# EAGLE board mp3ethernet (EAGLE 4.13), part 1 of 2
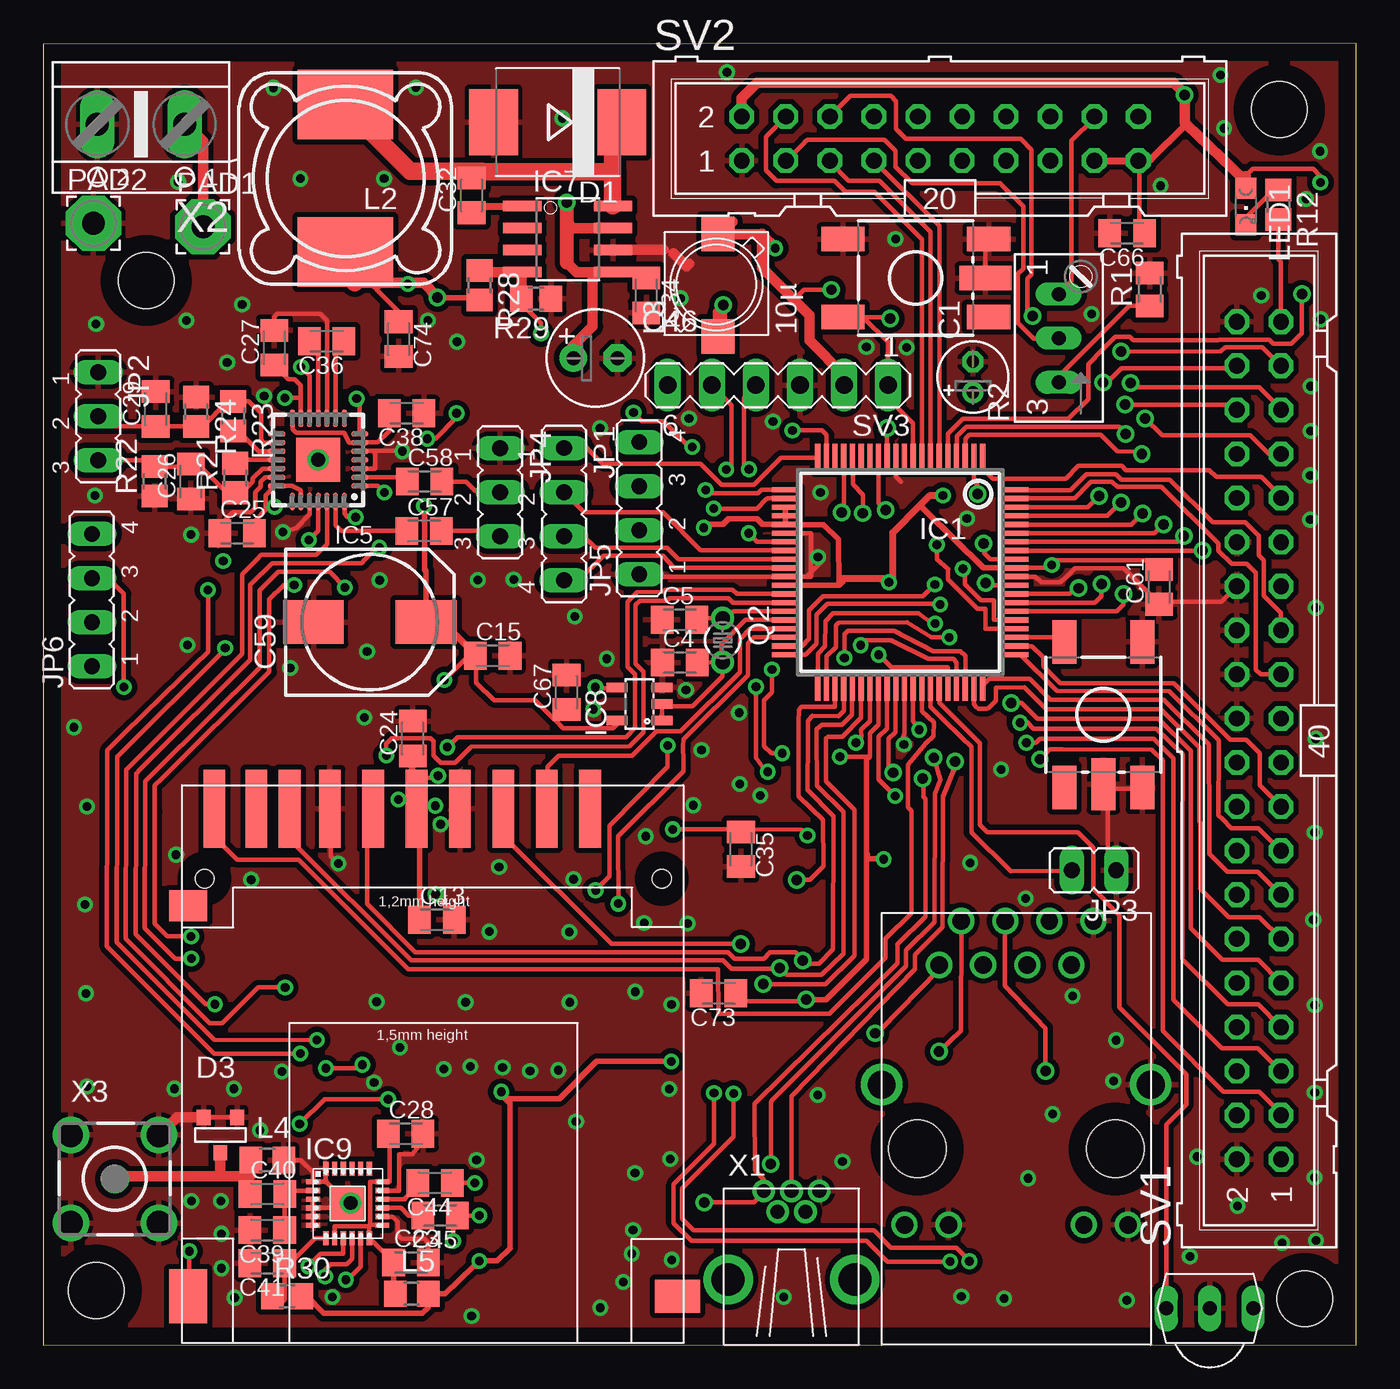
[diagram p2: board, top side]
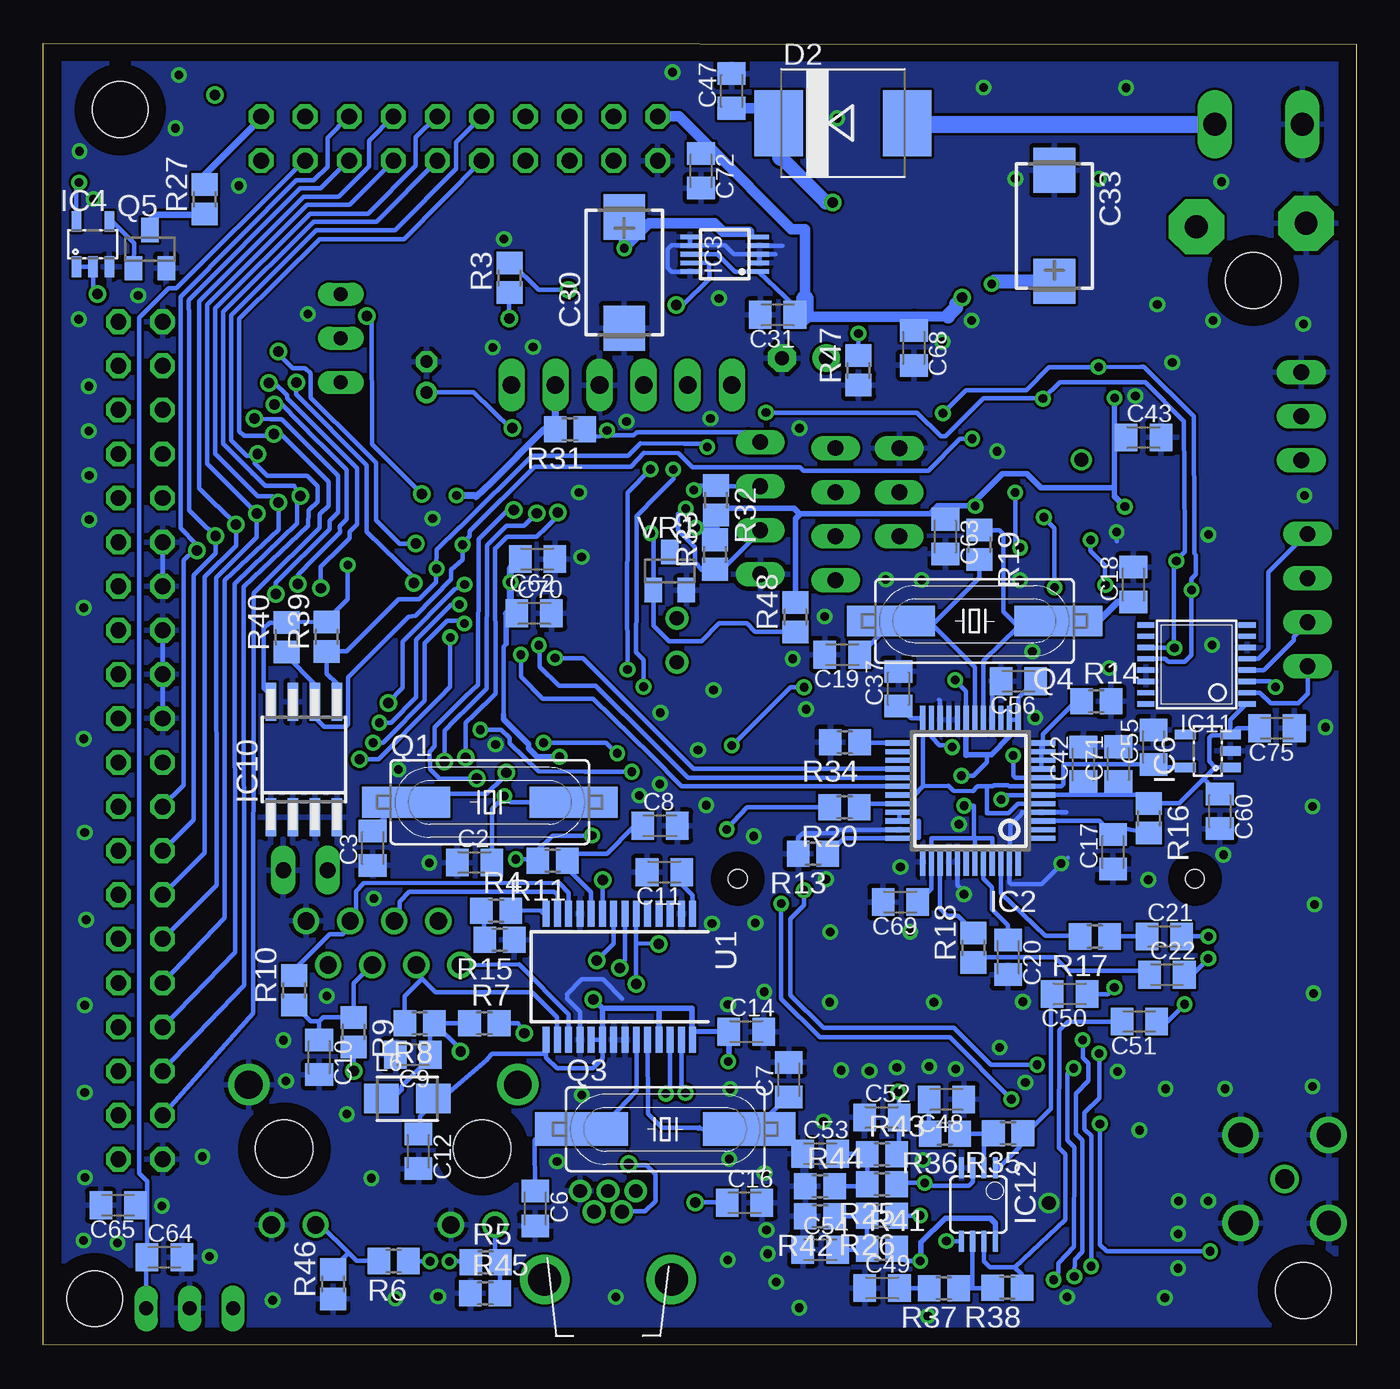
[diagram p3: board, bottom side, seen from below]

Size 75.66 x 75.02 mm. Coordinates in mm from the lower left corner, seen from the top.
Outline: 0,0 75.66,0.05 75.66,75.02 0,74.97 0,0
Copper layers (1*16): Top 0.035mm / dielectric 1.5mm / Bottom 0.035mm
Design rules "default": minimum track width 10mil, minimum drill 12mil, track to track 6mil, track to pad 6mil, pad to pad 6mil, via to via 6mil, smd to smd 0mil, copper to edge 40mil, drill to drill 8mil, minimum pad ring 10mil, minimum via ring 8mil, stop-mask expansion 2mil, vias tented up to drill 20mil, thermal gap 10mil
Holes 3.2 mm at 72.7,2.69 71.24,71.2 5.93,61.35 3.05,3.18

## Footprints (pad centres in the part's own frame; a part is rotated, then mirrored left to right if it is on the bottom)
1XRJ45_MM_JACK = drill 1 round: 1 4.445,-10.59; 2 3.175,-13.13; 3 1.905,-10.59; 4 0.635,-13.13; 5 -0.635,-10.59; 6 -1.905,-13.13; 7 -3.175,-10.59; 8 -4.445,-13.13; L1 3.9,4.38; L2 6.44,4.38; L3 -6.44,4.38; L4 -3.9,4.38 | drill 1.6 round: 9 7.75,-3.7; CASEGND -7.75,-3.7 | hole 3.3: 5.7,0; -5.7,0
E1,8-4 = drill 0.711 pad 1.168 round: + -0.889,0 | drill 0.711 pad 1.168 octagon: - 0.889,0
C0805K = smd 1.3 x 1.6: 1 -1,0; 2 1,0
CT7343 = smd 2.6 x 2.4: + 3.2,0; - -3.2,0
E2,5-6 = drill 0.813 pad 1.6 round: + -1.27,0 | drill 0.813 pad 1.6 octagon: - 1.27,0
150CLZ-0810 = smd 3.5 x 2.5: + 3.25,0; - -3.25,0
SDCA1A1401 = smd 1.25 x 4.5: 1 -6.63,4.04; 2 -9.13,4.04; 3 -11.63,4.04; 4 -14.13,4.04; 5 -16.63,4.04; 6 -19.13,4.04; 7 -21.45,4.04; 8 -23.36,4.04; 9 -4.13,4.04; 10 -25.79,4.04 | smd 2.2 x 1.8: 11 -27.3,-1.55 | smd 2.2 x 3.1: 12 -27.3,-24.05 | smd 2.6 x 1.9: 13 0.9,-24.05 | hole 1.06: 0,0; -26.35,0
SMC = smd 2.8 x 3.8: A 3.7,0; C -3.7,0
SOT-23 = smd 0.787 x 0.889: 1 0.025,-1.016; 2 -0.94,1.016; 3 0.991,1.016
SQFP-S-12X12-80 = smd 0.3 x 1.6: 1 -4.75,-6.6; 2 -4.25,-6.6; 3 -3.75,-6.6; 4 -3.25,-6.6; 5 -2.75,-6.6; 6 -2.25,-6.6; 7 -1.75,-6.6; 8 -1.25,-6.6; 9 -0.75,-6.6; 10 -0.25,-6.6; 11 0.25,-6.6; 12 0.75,-6.6; 13 1.25,-6.6; 14 1.75,-6.6; 15 2.25,-6.6; 16 2.75,-6.6; 17 3.25,-6.6; 18 3.75,-6.6; 19 4.25,-6.6; 20 4.75,-6.6; 41 4.75,6.6; 42 4.25,6.6; 43 3.75,6.6; 44 3.25,6.6; 45 2.75,6.6; 46 2.25,6.6; 47 1.75,6.6; 48 1.25,6.6; 49 0.75,6.6; 50 0.25,6.6; 51 -0.25,6.6; 52 -0.75,6.6; 53 -1.25,6.6; 54 -1.75,6.6; 55 -2.25,6.6; 56 -2.75,6.6; 57 -3.25,6.6; 58 -3.75,6.6; 59 -4.25,6.6; 60 -4.75,6.6 | smd 1.6 x 0.3: 21 6.6,-4.75; 22 6.6,-4.25; 23 6.6,-3.75; 24 6.6,-3.25; 25 6.6,-2.75; 26 6.6,-2.25; 27 6.6,-1.75; 28 6.6,-1.25; 29 6.6,-0.75; 30 6.6,-0.25; 31 6.6,0.25; 32 6.6,0.75; 33 6.6,1.25; 34 6.6,1.75; 35 6.6,2.25; 36 6.6,2.75; 37 6.6,3.25; 38 6.6,3.75; 39 6.6,4.25; 40 6.6,4.75; 61 -6.6,4.75; 62 -6.6,4.25; 63 -6.6,3.75; 64 -6.6,3.25; 65 -6.6,2.75; 66 -6.6,2.25; 67 -6.6,1.75; 68 -6.6,1.25; 69 -6.6,0.75; 70 -6.6,0.25; 71 -6.6,-0.25; 72 -6.6,-0.75; 73 -6.6,-1.25; 74 -6.6,-1.75; 75 -6.6,-2.25; 76 -6.6,-2.75; 77 -6.6,-3.25; 78 -6.6,-3.75; 79 -6.6,-4.25; 80 -6.6,-4.75
SQFP-S-7X7-48 = smd 0.3 x 1.6: 1 -2.75,-4.1; 2 -2.25,-4.1; 3 -1.75,-4.1; 4 -1.25,-4.1; 5 -0.75,-4.1; 6 -0.25,-4.1; 7 0.25,-4.1; 8 0.75,-4.1; 9 1.25,-4.1; 10 1.75,-4.1; 11 2.25,-4.1; 12 2.75,-4.1; 25 2.75,4.1; 26 2.25,4.1; 27 1.75,4.1; 28 1.25,4.1; 29 0.75,4.1; 30 0.25,4.1; 31 -0.25,4.1; 32 -0.75,4.1; 33 -1.25,4.1; 34 -1.75,4.1; 35 -2.25,4.1; 36 -2.75,4.1 | smd 1.6 x 0.3: 13 4.1,-2.75; 14 4.1,-2.25; 15 4.1,-1.75; 16 4.1,-1.25; 17 4.1,-0.75; 18 4.1,-0.25; 19 4.1,0.25; 20 4.1,0.75; 21 4.1,1.25; 22 4.1,1.75; 23 4.1,2.25; 24 4.1,2.75; 37 -4.1,2.75; 38 -4.1,2.25; 39 -4.1,1.75; 40 -4.1,1.25; 41 -4.1,0.75; 42 -4.1,0.25; 43 -4.1,-0.25; 44 -4.1,-0.75; 45 -4.1,-1.25; 46 -4.1,-1.75; 47 -4.1,-2.25; 48 -4.1,-2.75
MSOP10 = smd 0.27 x 1.1: 1 -1,-2; 2 -0.5,-2; 3 0,-2; 4 0.5,-2; 5 1,-2; 6 1,2; 7 0.5,2; 8 0,2; 9 -0.5,2; 10 -1,2
SOT23-5 = smd 0.55 x 1.2: 1 -0.95,-1.3; 2 0,-1.3; 3 0.95,-1.3; 4 0.95,1.3; 5 -0.95,1.3
QFN-28 = smd 1 x 0.3: 1 -2.4,1.5; 2 -2.4,1; 3 -2.4,0.5; 4 -2.4,0; 5 -2.4,-0.5; 6 -2.4,-1; 7 -2.4,-1.5; 15 2.4,-1.5; 16 2.4,-1; 17 2.4,-0.5; 18 2.4,0; 19 2.4,0.5; 20 2.4,1; 21 2.4,1.5 | smd 0.3 x 1: 8 -1.5,-2.4; 9 -1,-2.4; 10 -0.5,-2.4; 11 0,-2.4; 12 0.5,-2.4; 13 1,-2.4; 14 1.5,-2.4; 22 1.5,2.4; 23 1,2.4; 24 0.5,2.4; 25 0,2.4; 26 -0.5,2.4; 27 -1,2.4; 28 -1.5,2.4 | smd 2.54 x 2.54: THERMAL 0,0
SO08 = smd 0.61 x 2.21: 1 -1.905,-2.616; 2 -0.635,-2.616; 3 0.635,-2.616; 4 1.905,-2.616; 5 1.905,2.616; 6 0.635,2.616; 7 -0.635,2.616; 8 -1.905,2.616
S-PQFP-N24(RGE) = smd 0.8 x 0.3: 1 -2.5,1.75; 2 -2.5,1.25; 3 -2.5,0.75; 4 -2.5,0.25; 5 -2.5,-0.25; 6 -2.5,-0.75; 13 1.5,-0.75; 14 1.5,-0.25; 15 1.5,0.25; 16 1.5,0.75; 17 1.5,1.25; 18 1.5,1.75 | smd 0.3 x 0.8: 7 -1.75,-1.5; 8 -1.25,-1.5; 9 -0.75,-1.5; 10 -0.25,-1.5; 11 0.25,-1.5; 12 0.75,-1.5; 19 0.75,2.5; 20 0.25,2.5; 21 -0.25,2.5; 22 -0.75,2.5; 23 -1.25,2.5; 24 -1.75,2.5 | smd 1.999 x 1.999: GNDPAD -0.508,0.521
SO-08M = smd 0.6 x 2.2: 1 -1.905,-3.33; 2 -0.635,-3.33; 3 0.635,-3.33; 4 1.905,-3.33; 5 1.905,3.33; 6 0.635,3.33; 7 -0.635,3.33; 8 -1.905,3.33
TSSOP16 = smd 0.305 x 0.991: 1 -2.275,-2.918; 2 -1.625,-2.918; 3 -0.975,-2.918; 4 -0.325,-2.918; 5 0.325,-2.918; 6 0.975,-2.918; 7 1.625,-2.918; 8 2.275,-2.918; 9 2.275,2.918; 10 1.625,2.918; 11 0.975,2.918; 12 0.325,2.918; 13 -0.325,2.918; 14 -0.975,2.918; 15 -1.625,2.918; 16 -2.275,2.918
MSOP08 = smd 0.3 x 1.2: 1 -0.976,-2.113; 2 -0.326,-2.113; 3 0.324,-2.113; 4 0.974,-2.113; 5 0.974,2.112; 6 0.324,2.112; 7 -0.326,2.112; 8 -0.976,2.112
TSOP18XX = drill 0.813 long: GND -0.001,-0.027; OUT -2.501,-0.027; VCC 2.499,-0.027
JP4 = drill 0.914 long: 1 -3.81,0; 2 -1.27,0; 3 1.27,0; 4 3.81,0
JP2 = drill 0.914 long: 1 -2.54,0; 2 0,0; 3 2.54,0
JP1 = drill 0.914 long: 1 0,-1.27; 2 0,1.27
MSS1260 = smd 5.5 x 4: P$1 0,4.25; P$2 0,-4.25
PIS2408 = smd 1.9 x 2: P$1 0.1,-3.1; P$2 0.1,2.8
L0805 = smd 1.3 x 1.5: 1 -0.95,0; 2 0.95,0
PM1210 = smd 2 x 1.7: 1 -1.5,0; 2 1.5,0
CHIPLED_0805 = smd 1.2 x 1.2: A 0,-1.05; C 0,1.05
3,17/1,3 = drill 1.321 pad 3.175 octagon: 1 0,0
SM49 = smd 5.08 x 1.778: 1 -4.826,0; 2 4.826,0
TC26V = drill 0.813 round: 1 -1.27,0; 2 1.27,0
HC49UP = smd 5.334 x 1.93: 1 -4.826,0; 2 4.826,0
SOT23 = smd 1 x 1.4: 1 -0.95,-1.1; 2 0.95,-1.1; 3 0,1.1
M0805 = smd 1.3 x 1.6: 1 -0.95,0; 2 0.95,0
S64W = drill 0.813 long: A 2.54,1.27; E -2.54,1.27; S 0,1.27
R0805 = smd 1.3 x 1.5: 1 -0.85,0; 2 0.85,0
TASTER9313 = smd 2.5 x 1.4: 1 -4.2,2.25; 2 4.2,2.25; 3 -4.2,-2.25; 4 4.2,-2.25 | smd 3 x 1.4: GND 4,0
ML40 = drill 0.914 octagon: 1 -24.13,-1.27; 2 -24.13,1.27; 3 -21.59,-1.27; 4 -21.59,1.27; 5 -19.05,-1.27; 6 -19.05,1.27; 7 -16.51,-1.27; 8 -16.51,1.27; 9 -13.97,-1.27; 10 -13.97,1.27; 11 -11.43,-1.27; 12 -11.43,1.27; 13 -8.89,-1.27; 14 -8.89,1.27; 15 -6.35,-1.27; 16 -6.35,1.27; 17 -3.81,-1.27; 18 -3.81,1.27; 19 -1.27,-1.27; 20 -1.27,1.27; 21 1.27,-1.27; 22 1.27,1.27; 23 3.81,-1.27; 24 3.81,1.27; 25 6.35,-1.27; 26 6.35,1.27; 27 8.89,-1.27; 28 8.89,1.27; 29 11.43,-1.27; 30 11.43,1.27; 31 13.97,-1.27; 32 13.97,1.27; 33 16.51,-1.27; 34 16.51,1.27; 35 19.05,-1.27; 36 19.05,1.27; 37 21.59,-1.27; 38 21.59,1.27; 39 24.13,-1.27; 40 24.13,1.27
ML20 = drill 0.914 octagon: 1 -11.43,-1.27; 2 -11.43,1.27; 3 -8.89,-1.27; 4 -8.89,1.27; 5 -6.35,-1.27; 6 -6.35,1.27; 7 -3.81,-1.27; 8 -3.81,1.27; 9 -1.27,-1.27; 10 -1.27,1.27; 11 1.27,-1.27; 12 1.27,1.27; 13 3.81,-1.27; 14 3.81,1.27; 15 6.35,-1.27; 16 6.35,1.27; 17 8.89,-1.27; 18 8.89,1.27; 19 11.43,-1.27; 20 11.43,1.27
MA06-1 = drill 1.016 long: 1 -6.35,0; 2 -3.81,0; 3 -1.27,0; 4 1.27,0; 5 3.81,0; 6 6.35,0
SSOP28 = smd 0.4 x 1.5: 1 -4.225,-3.625; 2 -3.575,-3.625; 3 -2.925,-3.625; 4 -2.275,-3.625; 5 -1.625,-3.625; 6 -0.975,-3.625; 7 -0.325,-3.625; 8 0.325,-3.625; 9 0.975,-3.625; 10 1.625,-3.625; 11 2.275,-3.625; 12 2.925,-3.625; 13 3.575,-3.625; 14 4.225,-3.625; 15 4.225,3.625; 16 3.575,3.625; 17 2.925,3.625; 18 2.275,3.625; 19 1.625,3.625; 20 0.975,3.625; 21 0.325,3.625; 22 -0.325,3.625; 23 -0.975,3.625; 24 -1.625,3.625; 25 -2.275,3.625; 26 -2.925,3.625; 27 -3.575,3.625; 28 -4.225,3.625
USB-MB-H = drill 0.8 round: D+ 5.1,0; D- 3.9,0.8; GND 5.1,-1.6; ID 3.9,-0.8; VBUS 5.1,1.6 | drill 1.9 round: P$6 0,-3.65; P$7 0,3.65
AK500/2 = drill 1.321 long: 1 -2.515,0; 2 2.515,0
BU-SMB-V = drill 1.1 round: 1 0,0 | drill 1.4 round: 2 -2.54,2.54; 3 2.54,2.54; 4 2.54,-2.54; 5 -2.54,-2.54

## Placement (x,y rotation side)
BU1  [1XRJ45_MM_JACK]  56.07,11.33 180 top
C1  10µ  [E1,8-4]  53.57,55.79 90 top
C2  22p  [C0805K]  50.81,27.82 0 bottom
C3  22p  [C0805K]  56.68,28.65 90 bottom
C4  22p  [C0805K]  36.68,39.35 0 top
C5  22p  [C0805K]  36.67,41.81 0 top
C6  22p  [C0805K]  47.31,7.89 270 bottom
C7  22p  [C0805K]  32.7,15.31 90 bottom
C8  10µ  [C0805K]  40.12,29.94 0 bottom
C9  10n  [C0805K]  54.36,16.75 180 bottom
C10  10n  [C0805K]  59.77,16.6 270 bottom
C11  10µ  [C0805K]  39.87,27.27 180 bottom
C12  100n  [C0805K]  54.04,11.19 270 bottom
C13  100n  [C0805K]  22.68,24.53 0 top
C14  100n  [C0805K]  35.15,18.08 0 bottom
C15  1µ  [C0805K]  25.9,39.74 0 top
C16  100n  [C0805K]  35.25,8.22 0 bottom
C17  100n  [C0805K]  14.01,28.44 90 bottom
C18  22p  [C0805K]  12.84,43.85 90 bottom
C19  22p  [C0805K]  29.62,39.79 180 bottom
C20  100n  [C0805K]  20.06,22.37 270 bottom
C21  1µ  [C0805K]  11.05,23.56 0 bottom
C22  1µ  [C0805K]  10.9,21.37 0 bottom
C23  100n  [C0805K]  21.19,4.78 0 top
C24  1µ  [C0805K]  21.29,34.97 90 top
C25  1µ  [C0805K]  11.17,46.79 0 top
C26  100n  [C0805K]  8.5,49.78 90 top
C27  1µ  [C0805K]  13.31,57.49 90 top
C28  100n  [C0805K]  20.88,12.2 0 top
C29  100n  [C0805K]  6.48,53.95 90 top
C30  100µ  [CT7343]  42.18,61.82 90 bottom
C31  10µ  [C0805K]  33.34,59.38 180 bottom
C32  10n  [C0805K]  24.68,66.26 90 top
C33  100µ  [CT7343]  17.39,64.51 270 bottom
C34  1µ  [C0805K]  34.75,60.5 270 top
C35  100n  [C0805K]  40.2,28.59 270 top
C36  1µ  [C0805K]  16.32,57.85 180 top
C37  1µ  [C0805K]  26.38,37.84 90 bottom
C38  1µ  [C0805K]  20.93,53.71 180 top
C39  22p  [C0805K]  12.91,6.65 180 top
C40  100p  [C0805K]  12.92,8.73 0 top
C41  100n  [C0805K]  12.91,4.74 180 top
C42  100n  [C0805K]  15.73,33.48 90 bottom
C43  100n  [C0805K]  12.25,52.32 0 bottom
C44  100n  [C0805K]  22.57,9.37 180 top
C45  100n  [C0805K]  22.86,7.49 180 top
C46  100µ  [E2,5-6]  31.82,56.89 0 top
C47  100n  [C0805K]  36,72.28 90 bottom
C48  100n  [C0805K]  23.61,14.18 180 bottom
C49  100n  [C0805K]  27.32,3.31 0 bottom
C50  1µ  [C0805K]  16.51,20.25 180 bottom
C51  1µ  [C0805K]  12.5,18.66 180 bottom
C52  100n  [C0805K]  27.33,13.14 0 bottom
C53  100n  [C0805K]  30.89,11.04 0 bottom
C54  100n  [C0805K]  30.89,5.52 0 bottom
C55  1µ  [C0805K]  11.68,34.47 90 bottom
C56  1µ  [C0805K]  19.46,38.27 180 bottom
C57  1µ  [C0805K]  21.95,46.93 0 top
C58  1µ  [C0805K]  21.97,49.78 0 top
C59  1000µ  [150CLZ-0810]  18.81,41.67 0 top
C60  1µ  [C0805K]  7.85,30.78 270 bottom
C61  100n  [C0805K]  64.3,43.71 90 top
C62  100n  [C0805K]  47.18,45.31 180 bottom
C63  100n  [C0805K]  23.68,46.6 270 bottom
C64  1µ  [C0805K]  68.69,5.09 0 bottom
C65  100n  [C0805K]  71.35,8.08 180 bottom
C66  1µ  [C0805K]  62.46,64.08 180 top
C67  100n  [C0805K]  30.15,37.64 90 top
C68  1µ  [C0805K]  25.49,57.47 270 bottom
C69  100n  [C0805K]  26.27,25.54 180 bottom
C70  100n  [C0805K]  47.37,42.18 0 bottom
C71  1µ  [C0805K]  13.71,33.5 90 bottom
C72  100n  [C0805K]  37.76,67.68 270 bottom
C73  100n  [C0805K]  38.92,20.29 180 top
C74  100n  [C0805K]  20.48,57.98 270 top
C75  100n  [C0805K]  4.56,35.57 180 bottom
CON1  SCDA1A1401  [SDCA1A1401]  35.64,26.89 0 top
D1  MBRS 340  [SMC]  29.65,70.48 180 top
D2  MBRS 340  [SMC]  29.57,70.43 0 bottom
D3  [SOT-23]  10.18,12.12 0 top
IC1  PIC18F87J50  [SQFP-S-12X12-80]  49.38,44.55 180 top
IC2  VS1033  [SQFP-S-7X7-48]  22.23,31.97 90 bottom
IC3  TPS62056  [MSOP10]  36.39,62.87 90 bottom
IC4  74AHCT1G08  [SOT23-5]  72.81,63.45 0 bottom
IC5  MAX9729  [QFN-28]  15.84,51.02 180 top
IC6  TPS73225  [SOT23-5]  8.54,34.26 90 bottom
IC7  TPS54X0  [SO08]  30.22,63.75 270 top
IC8  74AHC1G08  [SOT23-5]  34.36,36.96 90 top
IC9  SI4701  [S-PQFP-N24(RGE)]  18.04,7.68 0 top
IC10  24xx1025  [SO-08M]  60.65,33.76 0 bottom
IC11  TSC2003  [TSSOP16]  9.2,39.24 90 bottom
IC12  OPA2340EA  [MSOP08]  21.77,8.12 180 bottom
IC13  TSOP1836  [TSOP18XX]  67.22,2.16 0 top
JP1  [JP4]  30,47.9 270 top
JP2  [JP2]  3.17,53.54 270 top
JP3  [JP1]  60.56,27.39 90 top
JP4  [JP2]  26.33,49.15 270 top
JP5  [JP4]  34.34,48.24 90 top
JP6  [JP4]  2.8,42.94 90 top
L2  33µH  [MSS1260]  17.42,67.24 180 top
L3  10µ  [PIS2408]  38.79,61.23 0 top
L4  100nH  [L0805]  12.91,10.69 0 top
L5  100nH  [L0805]  21.23,2.99 0 top
L6  10µ  [PM1210]  54.68,14.22 0 bottom
LED1  [CHIPLED_0805]  69.31,65.63 180 top
PAD1  [3,17/1,3]  9.2,64.45 0 top
PAD2  [3,17/1,3]  2.89,64.66 0 top
Q1  12MHz  [SM49]  49.94,31.3 0 bottom
Q2  32,768kHz  [TC26V]  39.15,40.63 270 top
Q3  25MHz  [HC49UP]  39.81,12.46 0 bottom
Q4  12,288MHz  [SM49]  21.99,41.74 180 bottom
Q5  IRLML2402  [SOT23]  69.52,63.16 0 bottom
R1  1k  [M0805]  63.76,60.84 90 top
R2  10k  [S64W]  59.8,58.03 90 top
R3  10k  [R0805]  48.8,61.51 90 bottom
R4  2k2  [R0805]  49.57,25.05 0 bottom
R5  180  [R0805]  50.17,4.8 0 bottom
R6  180  [R0805]  55.47,4.87 180 bottom
R7  50  [R0805]  50.25,18.57 0 bottom
R8  50  [R0805]  53.98,18.57 180 bottom
R9  50  [R0805]  57.77,18.06 270 bottom
R10  50  [R0805]  61.22,20.47 90 bottom
R11  10k  [R0805]  46.31,27.92 180 bottom
R12  2k2  [R0805]  71.16,65.73 270 top
R13  100k  [R0805]  31.3,28.33 180 bottom
R14  100k  [R0805]  14.98,37.11 0 bottom
R15  120  [R0805]  49.37,23.37 180 bottom
R16  100k  [R0805]  11.94,30.38 270 bottom
R17  10  [R0805]  15.05,23.56 180 bottom
R18  10  [R0805]  22.06,22.92 90 bottom
R19  1M  [R0805]  21.71,46.13 270 bottom
R20  100k  [R0805]  29.48,31.02 180 bottom
R21  47k  [R0805]  11.05,49.98 90 top
R22  22k  [R0805]  6.4,49.79 90 top
R23  47k  [R0805]  10.94,53.55 270 top
R24  22k  [R0805]  8.82,53.79 270 top
R25  1M  [R0805]  27.33,9.29 180 bottom
R26  1M  [R0805]  27.33,7.49 180 bottom
R27  22  [R0805]  66.36,66.03 90 bottom
R28  10k  [R0805]  25.14,61.08 270 top
R29  10k  [R0805]  28.4,60.32 180 top
R30  10k  [R0805]  14.05,2.84 0 top
R31  10k  [R0805]  45.32,52.8 180 bottom
R32  10k  [R0805]  36.88,48.7 270 bottom
R33  10k  [R0805]  36.96,45.57 90 bottom
R34  100k  [R0805]  29.46,34.77 180 bottom
R35  3k3  [R0805]  20.06,12.22 180 bottom
R36  1k  [R0805]  23.7,12.2 180 bottom
R37  1k  [R0805]  23.75,3.31 180 bottom
R38  3k3  [R0805]  20.1,3.32 180 bottom
R39  1k  [R0805]  59.33,40.84 90 bottom
R40  1k  [R0805]  61.64,40.8 90 bottom
R41  2k2  [R0805]  27.33,5.58 0 bottom
R42  1k2  [R0805]  30.89,7.45 180 bottom
R43  2k2  [R0805]  27.33,11.02 0 bottom
R44  1k2  [R0805]  30.89,9.17 0 bottom
R45  10k  [R0805]  50.19,3.02 0 bottom
R46  10k  [R0805]  58.97,3.54 90 bottom
R47  4k7  [R0805]  28.68,56.18 90 bottom
R48  1k  [R0805]  32.33,41.97 90 bottom
S1  TASTER9313  [TASTER9313]  61.09,36.34 270 top
S3  TASTER9313  [TASTER9313]  50.28,61.5 0 top
SV1  [ML40]  70.06,34.85 90 top
SV2  [ML20]  51.68,69.54 0 top
SV3  [MA06-1]  42.34,55.33 180 top
U1  ENC28J60-SSOP  [SSOP28]  42.46,21.25 180 bottom
VR1  LM4040M3 3.0V  [SOT23]  39.55,44.62 0 bottom
X1  USB-MB-H  [USB-MB-H]  43.12,3.8 90 top
X2  [AK500/2]  5.63,70.36 180 top
X3  [BU-SMB-V]  4.12,9.59 0 top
